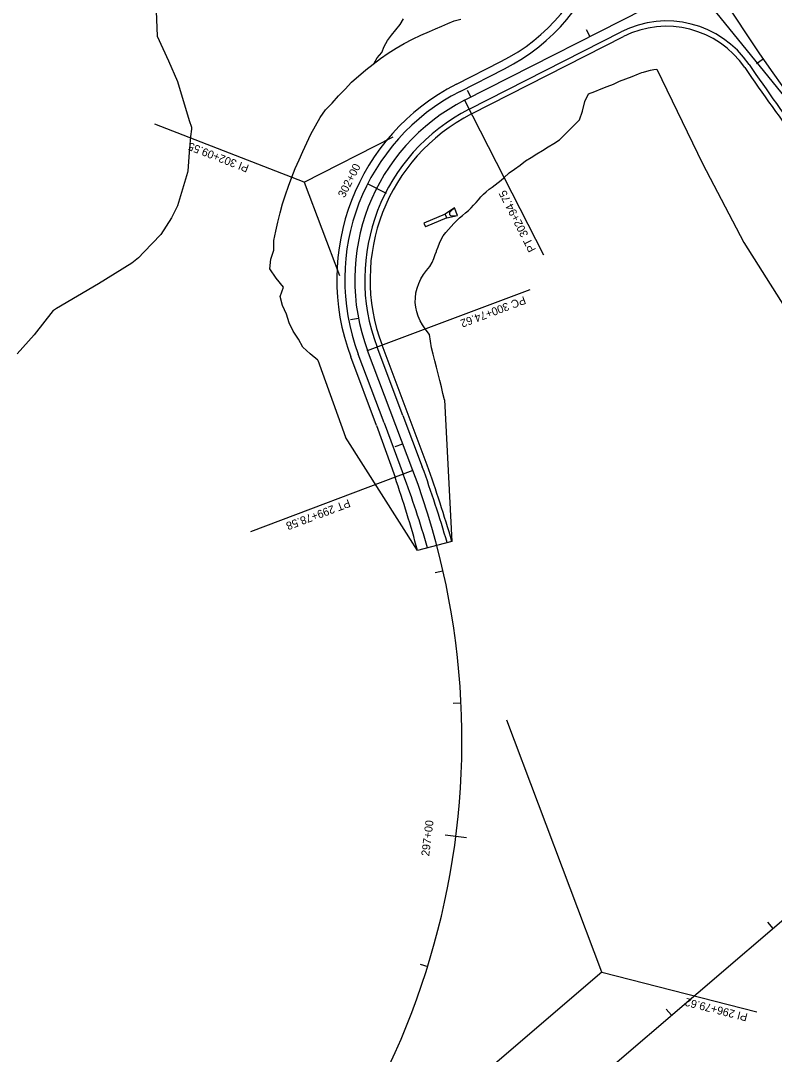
# Model space of a CAD drawing. Extents: x 916431 to 921570, y 1763982 to 1768032.
# Drawn here: x 918187 to 918752, y 1764755 to 1765530 of the extents above; entities that cross this region are included whole.
import ezdxf

# ---------------------------------------------------------------- set-up
doc = ezdxf.new("R2010")
doc.units = 0
for name, color, linetype in [('43', 7, 'Continuous'), ('R_Drainage', 7, 'Continuous'), ('R_Horz Alg', 7, 'Continuous'), ('R_Horz Alg Annot', 7, 'Continuous'), ('R_Horz Alg Stationing', 7, 'Continuous'), ('R_Proposed Const Limits', 7, 'Continuous'), ('R_Proposed Road', 7, 'Continuous'), ('R_SFHA', 7, 'Continuous'), ('R_Shld', 7, 'Continuous')]:
    doc.layers.add(name, color=color, linetype=linetype)

# ---------------------------------------------------------------- blocks, each defined once
blk = doc.blocks.new('36F_PL')
at = {"layer": '43'}
for p, q in [((0, 0), (-0.15, -0.815)), ((0, 0), (0.3, 0)), ((0.45, -0.815), (0.3, 0)), ((-0.007, -0.402), (-0.15, -0.815)), ((0.308, -0.402), (0.45, -0.815)), ((-0.15, -0.815), (0.45, -0.815))]:
    blk.add_line(p, q, dxfattribs=at)
blk.add_arc((0.15, -0.456), 0.167, 19.04262, 160.95738, dxfattribs=at)

msp = doc.modelspace()

# ---------------------------------------------------------------- linework, layer by layer
at = {"layer": 'R_Drainage'}
for p, q in [((918505.01, 1765384.9), (918489.02, 1765378.15)), ((918506.18, 1765382.14), (918490.19, 1765375.38)), ((918489.02, 1765378.15), (918490.19, 1765375.38))]:
    msp.add_line(p, q, dxfattribs=at)
at = {"layer": 'R_Horz Alg'}
for p, q in [((918522.67, 1764654.46), (919661.81, 1765630.35)), ((918519.58, 1765470.12), (918702.47, 1765563.28)), ((918480.78, 1765192.74), (918446.92, 1765282.61))]:
    msp.add_line(p, q, dxfattribs=at)
for centre, radius, start, end in [((920196.91, 1766498.5), 1762.95, 202.25028, 218.97694), ((918588.02, 1765335.77), 150.78, 116.99278, 200.64389), ((917944.61, 1764990.74), 572.96, 310.58639, 20.64389)]:
    msp.add_arc(centre, radius, start, end, dxfattribs=at)
at = {"layer": 'R_Horz Alg Annot'}
for p, q in [((918663.37, 1765591.08), (918777.08, 1765450.54)), ((918399.35, 1765408.88), (918466.12, 1765442.89)), ((918399.35, 1765408.88), (918425.77, 1765338.76)), ((918622.37, 1764816.91), (918551.29, 1765005.58)), ((918622.37, 1764816.91), (918469.26, 1764685.74))]:
    msp.add_line(p, q, dxfattribs=at)
for points in [[(918519.58, 1765470.12), (918578.59, 1765354.28)], [(918399.35, 1765408.88), (918287.46, 1765452.24)], [(918446.92, 1765282.61), (918568.57, 1765328.44)], [(918480.78, 1765192.74), (918359.13, 1765146.91)], [(918622.37, 1764816.91), (918738.61, 1764787.1)]]:
    msp.add_lwpolyline(points, dxfattribs=at)
at = {"layer": 'R_Horz Alg Stationing'}
for points in [[(918610.64, 1765523.24), (918613.36, 1765517.89)], [(918738.29, 1765497.69), (918743.24, 1765501.09)], [(918521.53, 1765477.85), (918524.26, 1765472.5)], [(918446.55, 1765407.86), (918460.8, 1765400.59)], [(918434.12, 1765305.86), (918440.01, 1765307)], [(918467.61, 1765210.67), (918473.23, 1765212.78)], [(918497.51, 1765116.21), (918503.36, 1765117.54)], [(918510.9, 1765018.29), (918516.89, 1765018.59)], [(918505.1, 1764919.79), (918520.97, 1764917.78)], [(918746.59, 1764854.2), (918750.5, 1764849.64)], [(918486.17, 1764822.95), (918491.9, 1764821.17)], [(918670.65, 1764789.14), (918674.55, 1764784.58)]]:
    msp.add_lwpolyline(points, dxfattribs=at)
at = {"layer": 'R_Proposed Const Limits'}
for p, q in [((918434.84, 1765483.61), (918445.44, 1765492.91)), ((918409.55, 1765275.3), (918430.26, 1765217.64)), ((918504.59, 1765245.64), (918510.07, 1765139.65)), ((918484.3, 1765132.87), (918430.26, 1765217.64))]:
    msp.add_line(p, q, dxfattribs=at)
for points in [[(918445.44, 1765492.91), (918450.96, 1765497.28), (918456.62, 1765501.45), (918462.41, 1765505.42), (918468.31, 1765509.18), (918474.34, 1765512.73), (918480.53, 1765515.95), (918486.82, 1765518.95), (918493.2, 1765521.73), (918497.83, 1765523.7), (918502.45, 1765525.65), (918507.07, 1765527.59), (918511.65, 1765529.62), (918516.62, 1765530.88)], [(918451.79, 1765497.89), (918454.09, 1765501.94), (918457.45, 1765505.84), (918459.37, 1765510.48), (918461.71, 1765514.9), (918464.84, 1765518.91), (918468, 1765522.91), (918471.19, 1765526.9), (918473.67, 1765531.25)], [(918612.45, 1765474.94), (918617.15, 1765476.73), (918621.79, 1765478.63), (918626.46, 1765480.47), (918631.14, 1765482.3), (918635.7, 1765484.38), (918640.36, 1765486.23), (918645.02, 1765488.1), (918649.73, 1765489.88), (918652.37, 1765490.87), (918653.51, 1765491.25), (918656.11, 1765492.05), (918658.74, 1765492.68), (918661.42, 1765493.15), (918663.54, 1765493.36)], [(918663.54, 1765493.36), (918697.72, 1765422.89), (918728.86, 1765363.64), (918783.6, 1765276.66), (918878.88, 1765122.86)], [(918409.55, 1765275.3), (918403.73, 1765280.07), (918398.31, 1765285.23), (918395.07, 1765291.16), (918391.03, 1765297.06), (918388.1, 1765303.33), (918386.12, 1765309.84), (918383.14, 1765316.34), (918381.28, 1765323.06), (918383.79, 1765330), (918378.49, 1765336.8), (918373.66, 1765343.94), (918374.39, 1765351.02), (918376.6, 1765357.93), (918376.65, 1765365.03), (918378.06, 1765371.97), (918379.6, 1765378.87), (918381.02, 1765384.73), (918381.28, 1765385.72), (918383.17, 1765392.51), (918385.3, 1765399.23), (918387.61, 1765405.88), (918390.06, 1765412.48), (918392.74, 1765418.99), (918395.51, 1765425.47), (918398.43, 1765431.88), (918401.38, 1765438.3), (918404.44, 1765444.7), (918407.8, 1765450.95), (918411.33, 1765457.13), (918415.35, 1765462.99), (918420.36, 1765468.1), (918424.97, 1765473.47), (918430.04, 1765478.43), (918434.84, 1765483.61)], [(918504.59, 1765245.64), (918503.36, 1765250.52), (918502.15, 1765255.41), (918500.94, 1765260.29), (918499.72, 1765265.18), (918498.5, 1765270.06), (918497.27, 1765274.94), (918496.05, 1765279.83), (918494.84, 1765284.71), (918494.01, 1765289.74), (918493.16, 1765294.76), (918490.12, 1765298.94), (918488.01, 1765301.89), (918486.22, 1765305), (918484.77, 1765308.27), (918483.68, 1765311.65), (918482.96, 1765315.12), (918482.62, 1765318.67), (918482.69, 1765322.24), (918483.12, 1765325.82), (918483.93, 1765329.37), (918485.16, 1765332.87), (918486.76, 1765336.27), (918488.7, 1765339.56), (918490.94, 1765342.7), (918493.56, 1765345.67), (918495.27, 1765348.61), (918496.4, 1765351.57), (918497.54, 1765354.48), (918498.43, 1765356.96), (918498.58, 1765357.38), (918499.69, 1765360.24), (918500.87, 1765363.05), (918502.11, 1765365.82), (918503.47, 1765368.53), (918505.42, 1765370.97), (918507.4, 1765373.33), (918509.42, 1765375.62), (918511.48, 1765377.81), (918513.57, 1765379.94), (918515.69, 1765381.99), (918517.98, 1765383.88), (918520.24, 1765385.71), (918522.51, 1765387.47), (918524.36, 1765389.54), (918526.22, 1765391.58), (918528.14, 1765393.55), (918529.95, 1765395.65), (918531.74, 1765397.8), (918533.66, 1765399.83), (918535.79, 1765401.63), (918537.92, 1765403.43), (918540.15, 1765405.11), (918542.4, 1765406.78), (918544.68, 1765408.43), (918546.83, 1765410.33), (918549.06, 1765412.17), (918552.84, 1765415.71), (918556.95, 1765418.66), (918561.12, 1765421.47), (918565.07, 1765424.75), (918569.34, 1765427.39), (918573.61, 1765430.01), (918577.91, 1765432.58), (918582.22, 1765435.15), (918586.49, 1765437.76), (918590.68, 1765440.56), (918594.39, 1765444.29), (918598.09, 1765448.04), (918601.87, 1765451.64), (918605.54, 1765455.45), (918607.83, 1765461.98), (918609.69, 1765469.34), (918612.45, 1765474.94)]]:
    msp.add_lwpolyline(points, dxfattribs=at)
at = {"layer": 'R_Proposed Road'}
for p, q in [((918522.99, 1765463.44), (918636.81, 1765521.42)), ((918516.18, 1765476.81), (918549.52, 1765493.79)), ((918473.31, 1765233.85), (918453.94, 1765285.26)), ((918459.27, 1765228.56), (918439.9, 1765279.97)), ((918459.27, 1765228.56), (918473.55, 1765190.01)), ((918473.31, 1765233.85), (918487.89, 1765195.42)), ((918510.07, 1765139.65), (918484.3, 1765132.87))]:
    msp.add_line(p, q, dxfattribs=at)
for centre, radius, start, end in [((918481.44, 1765627.45), 150, 296.99278, 26.91983), ((918670.85, 1765454.59), 75, 34.37448, 116.99278), ((920196.91, 1766498.5), 1773.95, 214.37448, 218.97694), ((918588.02, 1765335.77), 158.28, 116.99278, 200.64389), ((918588.02, 1765335.77), 143.28, 116.99278, 200.64389), ((917716.34, 1764909.24), 807.58, 16.22094, 20.34462), ((917583.8, 1764867.8), 961.62, 16.36307, 19.91937)]:
    msp.add_arc(centre, radius, start, end, dxfattribs=at)
at = {"layer": 'R_SFHA'}
msp.add_lwpolyline([(918288.28, 1765543.07), (918289.19, 1765518.11), (918297.7, 1765499.64), (918304.37, 1765484.12), (918313.26, 1765455.08), (918314.93, 1765450.12), (918314.86, 1765448.54), (918314.28, 1765442.93), (918313.26, 1765430.99), (918312.12, 1765417.27), (918311.9, 1765416.12), (918304.41, 1765390.95), (918300.08, 1765382.16), (918291.88, 1765369.51), (918279.3, 1765356.25), (918275.33, 1765352.09), (918270.29, 1765348.13), (918245.27, 1765332.71), (918213.85, 1765314.13), (918212.26, 1765313.17), (918211.29, 1765312.58), (918197.12, 1765294.39), (918184.27, 1765280.16)], dxfattribs=at)
at = {"layer": 'R_Shld'}
for p, q in [((918524.8, 1765459.88), (918638.62, 1765517.85)), ((918513.45, 1765482.15), (918546.79, 1765499.13)), ((918491.54, 1765196.79), (918457.68, 1765286.67)), ((918453.66, 1765226.44), (918434.29, 1765277.85)), ((918453.66, 1765226.44), (918467.46, 1765187.72))]:
    msp.add_line(p, q, dxfattribs=at)
for centre, radius, start, end in [((918481.44, 1765627.45), 144, 296.99278, 26.91983), ((918670.85, 1765454.59), 71, 34.37448, 116.99278), ((920196.91, 1766498.5), 1777.95, 214.37448, 218.97694), ((918588.02, 1765335.77), 164.28, 116.99278, 200.64389), ((918588.02, 1765335.77), 139.28, 116.99278, 200.64389), ((917358.61, 1764797.83), 1201.13, 16.53398, 19.39961), ((917650.24, 1764906.88), 864.13, 15.16019, 18.96539)]:
    msp.add_arc(centre, radius, start, end, dxfattribs=at)

# ---------------------------------------------------------------- block references
at = {"layer": 'R_Drainage', "xscale": 9.999999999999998, "yscale": 9.999999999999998, "rotation": 112.88735515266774}
msp.add_blockref('36F_PL', (918506.18, 1765382.14), dxfattribs=at)

# ---------------------------------------------------------------- texts
at = {"layer": 'R_Horz Alg Annot'}
for s, rotation, p in [('PI 302+09.55', 158.81833, (918358.52, 1765421.49)), ('PT 302+94.75', 116.99278, (918573.19, 1765358.27)), ('PC 300+74.62', 200.64389, (918564.02, 1765323.52)), ('PT 299+78.58', 200.64389, (918432.56, 1765171.37)), ('PI 296+79.62', 165.61514, (918732.05, 1764785.68))]:
    msp.add_text(s, height=6, rotation=rotation, dxfattribs=at).set_placement(p)
at = {"layer": 'R_Horz Alg Stationing'}
for s, rotation, p in [('302+00', 62.99946, (918429.62, 1765396.67)), ('297+00', 82.78592, (918492.96, 1764903.54))]:
    msp.add_text(s, height=6, rotation=rotation, dxfattribs=at).set_placement(p)

doc.saveas('drawing.dxf')
